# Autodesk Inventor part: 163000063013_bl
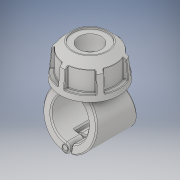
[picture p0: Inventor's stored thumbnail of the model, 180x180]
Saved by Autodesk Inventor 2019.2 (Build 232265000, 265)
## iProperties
Created: 2022-02
Part Number: 163000063013_bl
Material: Generic
Description: Plassadle Threaded 63x1 1/4''
Document SubType Name: Modeling
Designer: comp2
Density: 1 g/cm^3
Appearance: Default
Author: comp2
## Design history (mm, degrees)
derived "16300.ipt"
feature "Solid1::16300.ipt" dims "ScaleForDerivedMember" = 10
feature "Solid2::16300.ipt" dims "ScaleForDerivedMember" = 10
feature "Solid3::16300.ipt" dims "ScaleForDerivedMember" = 10
feature "Solid4::16300.ipt" dims "ScaleForDerivedMember" = 10
tag "TaggingFeature1"
body "Solid1"
body "Solid2"
body "Solid3"
body "Solid4"
other parameters: "d0" = 63 [user parameter], "d2" = 91 [user parameter], "d3" = 31.5 [user parameter], "d7" = 86.45 [user parameter], "d8" = 85 deg [user parameter], "d9" = 45 deg [user parameter], "d10" = 102 [user parameter], "d11" = 49 [user parameter], "d12" = 38.8185 [user parameter], "d13" = 42.84 [user parameter], "d14" = 58.428 [user parameter], "d42" = 2.8 [user parameter], "d49" = 1.82 [user parameter], "d50" = 89 [user parameter], "d51" = 0 [user parameter], "d52" = 19.6 [user parameter], "d53" = 50.05 [user parameter], "d54" = 31.15 [user parameter], "d55" = 0 [user parameter], "d56" = 17.8 [user parameter], "d57" = 17.8 [user parameter], "d59" = 0 [user parameter], "d60" = 89 [user parameter], "d61" = 0 [user parameter], "d62" = 31.15 [user parameter], "d63" = 0 [user parameter], "d65" = 0 [user parameter], "d67" = 0 [user parameter], "d69" = 0 [user parameter], "d70" = 1 [user parameter], "d71" = 85.44 [user parameter], "d72" = 0 [user parameter], "d73" = 2 [user parameter], "d78" = 86.7 [user parameter], "d79" = 5.1 [user parameter], "d80" = 60 deg [user parameter], "d81" = 5.1 [user parameter], "d84" = 0 [user parameter], "d85" = 1 [user parameter], "d87" = 360 deg [user parameter], "d122" = 58 [user parameter], "d124" = 42.80128 [user parameter], "d125" = 2.77275 [user parameter], "d127" = 146 [user parameter], "d129" = 38.952 [user parameter], "d130" = 33.1092 [user parameter], "d131" = 37.7 [user parameter], "d132" = 45 deg [user parameter], "d133" = 26.39 [user parameter], "d134" = 19.476 [user parameter], "d136" = 0 [user parameter], "d138" = 0 [user parameter], "d" = 63 [user parameter], "d1" = 25 [user parameter], "B" = 91 [user parameter], "L" = 89 [user parameter], "E_" = 54 [user parameter], "E1" = 102 [user parameter], "H1" = 146 [user parameter], "H2" = 58 [user parameter], "H3" = 78 [user parameter], "H_costum" = 49 [user parameter], "Rp" = 38.952 [user parameter], "d128" = 55.455 [user parameter]
